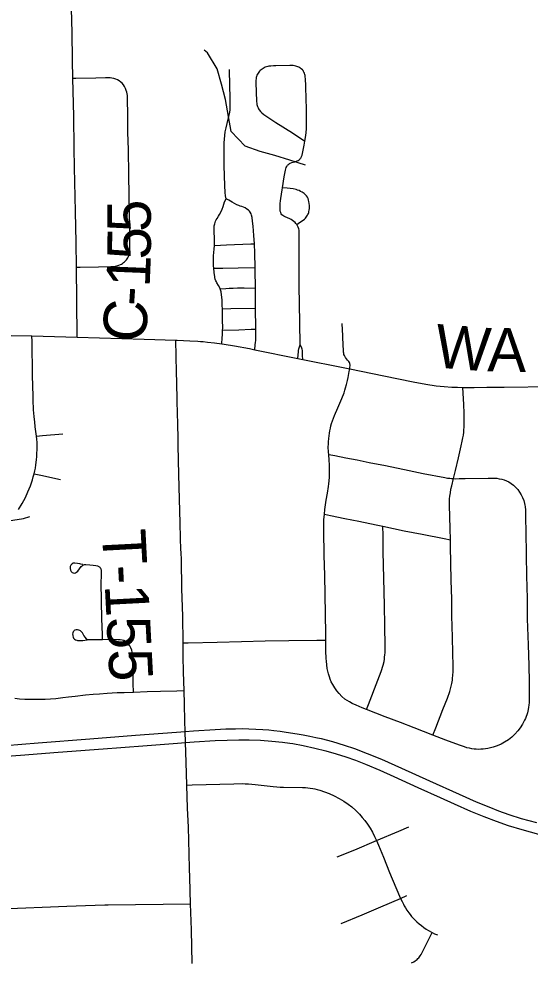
# Model space of a CAD drawing. Extents: x -6.4 to 34, y -4.2 to 22.
# Drawn here: x 5.927 to 6.594, y 17.467 to 18.698 of the extents above; entities that cross this region are included whole.
import ezdxf

# ---------------------------------------------------------------- set-up
doc = ezdxf.new("R2010")
doc.units = 0
for name, color, linetype in [('GM_X_County_Road', 7, 'Continuous'), ('GM_X_County_Road_Text', 7, 'Continuous'), ('GM_X_Minor_River', 7, 'Continuous'), ('GM_X_State_Route', 7, 'Continuous'), ('GM_X_Township_Road', 7, 'Continuous'), ('GM_X_Township_Road_Text', 7, 'Continuous')]:
    doc.layers.add(name, color=color, linetype=linetype)

msp = doc.modelspace()

# ---------------------------------------------------------------- linework, layer by layer
at = {"layer": 'GM_X_County_Road'}
for points in [[(6.0032, 18.2828), (6.0028, 18.3305), (6.0021, 18.3742), (6.0016, 18.4067), (6.0007, 18.4471), (5.9997, 18.5042), (5.9991, 18.5297), (5.9985, 18.5714), (5.9974, 18.6204), (5.9969, 18.6446), (5.9963, 18.6806), (5.9958, 18.7116)], [(5.9168, 18.2851), (5.9439, 18.2845), (6.0032, 18.2828), (6.0905, 18.2802), (6.1317, 18.279), (6.1334, 18.2789), (6.1502, 18.2783), (6.1607, 18.2777), (6.1639, 18.2774), (6.1676, 18.2771), (6.1731, 18.2766), (6.1824, 18.2757), (6.1918, 18.2744), (6.1948, 18.274), (6.2083, 18.2717), (6.2279, 18.268), (6.235, 18.2666), (6.2912, 18.2552), (6.2976, 18.2539), (6.3504, 18.2433), (6.3589, 18.2415), (6.4033, 18.2324), (6.4417, 18.2245), (6.4582, 18.2215), (6.4717, 18.2196), (6.4822, 18.2185), (6.4921, 18.2178), (6.4998, 18.2176), (6.5065, 18.2174), (6.5138, 18.2174), (6.5212, 18.2175), (6.538, 18.2177), (6.5604, 18.2179), (6.6226, 18.2185)]]:
    msp.add_lwpolyline(points, dxfattribs=at)
at = {"layer": 'GM_X_Minor_River'}
for points in [[(6.3012, 18.5073), (6.2808, 18.5139), (6.2611, 18.5201), (6.2418, 18.5251), (6.2226, 18.5324), (6.2041, 18.5515), (6.2005, 18.5709), (6.1965, 18.5929), (6.1913, 18.6131), (6.1857, 18.6332), (6.173, 18.6542), (6.1689, 18.6576)], [(5.9135, 18.0431), (5.9329, 18.0464), (5.9412, 18.0491)]]:
    msp.add_lwpolyline(points, dxfattribs=at)
at = {"layer": 'GM_X_State_Route'}
for points in [[(5.9096, 17.7503), (5.952, 17.7536), (6.0195, 17.7589), (6.0793, 17.7635), (6.1329, 17.7674), (6.1439, 17.7683), (6.1548, 17.7692), (6.183, 17.771), (6.1971, 17.7718), (6.2097, 17.7721), (6.2185, 17.7722), (6.2271, 17.772), (6.2361, 17.7716), (6.2455, 17.771), (6.2531, 17.7704), (6.2597, 17.7697), (6.2679, 17.7687), (6.276, 17.7676), (6.2902, 17.7654), (6.298, 17.7641), (6.3067, 17.7625), (6.3146, 17.7608), (6.3215, 17.7592), (6.3363, 17.7553), (6.3515, 17.7507), (6.365, 17.7462), (6.3818, 17.7398), (6.4002, 17.7322), (6.4263, 17.7206), (6.4631, 17.7039), (6.5017, 17.6866), (6.5239, 17.6768), (6.5405, 17.6699), (6.5533, 17.665), (6.5668, 17.6602), (6.5829, 17.6551), (6.6026, 17.6495)], [(6.0425, 17.7464), (6.0544, 17.7473), (6.1003, 17.7507), (6.1341, 17.7531), (6.1443, 17.7539), (6.156, 17.7548), (6.1831, 17.7566), (6.1989, 17.7573), (6.2139, 17.7577), (6.2276, 17.7576), (6.2425, 17.7569), (6.2573, 17.7559), (6.2711, 17.7544), (6.2808, 17.7531)], [(6.2808, 17.7531), (6.2846, 17.7526), (6.2983, 17.7501), (6.3132, 17.7468), (6.3276, 17.7433), (6.3413, 17.7394), (6.3539, 17.7355), (6.3664, 17.731), (6.3796, 17.7256), (6.398, 17.7179), (6.4163, 17.7099), (6.4479, 17.6955), (6.477, 17.6823), (6.4951, 17.6742), (6.5167, 17.6646), (6.5338, 17.6574), (6.5501, 17.6513), (6.5659, 17.6459), (6.5838, 17.6405), (6.6161, 17.6316), (6.6413, 17.6247), (6.6677, 17.6176), (6.6782, 17.6149)], [(5.7817, 17.7285), (5.798, 17.7291), (5.8313, 17.7309), (5.8489, 17.732), (5.8666, 17.733), (5.8939, 17.735), (5.9348, 17.7381), (5.9725, 17.741), (6.0135, 17.7442), (6.0425, 17.7464)]]:
    msp.add_lwpolyline(points, dxfattribs=at)
at = {"layer": 'GM_X_Township_Road'}
for points in [[(6.2793, 18.5089), (6.2803, 18.5095), (6.2813, 18.5099), (6.2835, 18.5107), (6.2873, 18.5119), (6.2901, 18.5129), (6.2916, 18.5137), (6.293, 18.5145), (6.2937, 18.5151), (6.2943, 18.5157), (6.2948, 18.5164), (6.2953, 18.5171), (6.2959, 18.5186), (6.2966, 18.5204), (6.2973, 18.5225), (6.2993, 18.5333), (6.3003, 18.5389), (6.3015, 18.5461), (6.302, 18.5501), (6.3025, 18.555), (6.3026, 18.5594), (6.3023, 18.5818), (6.3021, 18.5931), (6.3016, 18.6105), (6.3011, 18.6204), (6.3009, 18.6223), (6.3006, 18.6242), (6.3002, 18.6259), (6.2997, 18.6273), (6.2992, 18.6286), (6.2986, 18.6296), (6.2979, 18.6308), (6.2971, 18.6317), (6.2957, 18.6331), (6.2947, 18.6339), (6.2937, 18.6346), (6.2926, 18.6352), (6.2913, 18.6358), (6.2899, 18.6363), (6.2884, 18.6368), (6.2868, 18.6371), (6.285, 18.6373), (6.2832, 18.6375), (6.2807, 18.6375), (6.2626, 18.6372), (6.2592, 18.637), (6.2559, 18.6368), (6.2535, 18.6364), (6.2518, 18.6361), (6.2502, 18.6356), (6.2487, 18.6351), (6.2472, 18.6344), (6.2459, 18.6337), (6.2445, 18.6328), (6.2432, 18.6318), (6.242, 18.6308), (6.2411, 18.63), (6.2401, 18.6288), (6.2392, 18.6276), (6.2384, 18.6263), (6.2377, 18.6249), (6.2372, 18.6233), (6.2368, 18.6218), (6.2366, 18.6202), (6.2364, 18.6184), (6.2363, 18.6164), (6.2367, 18.6014), (6.2371, 18.5921), (6.2373, 18.5901), (6.2375, 18.5883), (6.2378, 18.5867), (6.2382, 18.5852), (6.2386, 18.5838), (6.2392, 18.5822), (6.2399, 18.5808), (6.2408, 18.5794), (6.2423, 18.5774), (6.2441, 18.5756), (6.2466, 18.5736), (6.2626, 18.5631), (6.284, 18.5496), (6.3003, 18.5389)], [(6.1821, 18.4284), (6.1827, 18.4308), (6.1831, 18.4326), (6.1837, 18.4343), (6.1845, 18.4362), (6.1857, 18.4378), (6.1877, 18.4408), (6.189, 18.4429), (6.1907, 18.4462), (6.1924, 18.45), (6.1936, 18.4535), (6.1946, 18.4565), (6.1956, 18.4594), (6.1976, 18.4634), (6.1968, 18.4676), (6.1963, 18.4717), (6.1957, 18.481), (6.1951, 18.5064), (6.195, 18.5151), (6.195, 18.5194), (6.1949, 18.5286), (6.1949, 18.5317), (6.195, 18.5366), (6.1953, 18.5415), (6.1964, 18.5507), (6.1975, 18.5561), (6.2004, 18.5676), (6.2019, 18.5743), (6.2027, 18.5793), (6.2029, 18.5827), (6.203, 18.585), (6.203, 18.5908), (6.2029, 18.5956), (6.2024, 18.6111), (6.2019, 18.6322)], [(6.0021, 18.3742), (6.007, 18.3742), (6.0308, 18.3746), (6.0469, 18.375), (6.0506, 18.3753), (6.0544, 18.3759), (6.056, 18.3763), (6.0576, 18.3769), (6.0595, 18.3777), (6.0611, 18.3784), (6.0624, 18.3792), (6.0637, 18.3802), (6.065, 18.3813), (6.0663, 18.3825), (6.0675, 18.3838), (6.0684, 18.3851), (6.0694, 18.3865), (6.0701, 18.3881), (6.0707, 18.3895), (6.0712, 18.391), (6.0715, 18.3925), (6.0717, 18.3941), (6.0719, 18.3976), (6.0719, 18.4014), (6.0719, 18.4112), (6.0716, 18.4259), (6.0713, 18.4451), (6.071, 18.4683), (6.0704, 18.495), (6.0699, 18.5279), (6.0694, 18.5502), (6.0693, 18.5708), (6.0688, 18.5957), (6.0686, 18.5981), (6.0683, 18.6005), (6.0678, 18.6027), (6.0671, 18.6049), (6.0662, 18.6073), (6.0649, 18.61), (6.0635, 18.6121), (6.0617, 18.6142), (6.0599, 18.6158), (6.0578, 18.6174), (6.0557, 18.6186), (6.0534, 18.6197), (6.0509, 18.6205), (6.0485, 18.621), (6.0462, 18.6212), (6.0401, 18.6212), (6.0275, 18.621), (6.0015, 18.6205), (5.9974, 18.6204)], [(6.2931, 18.4149), (6.2931, 18.4188), (6.293, 18.421), (6.2927, 18.4226), (6.2924, 18.4242), (6.2916, 18.4263), (6.2907, 18.4281), (6.2898, 18.4298), (6.2887, 18.4315), (6.2876, 18.4327), (6.2859, 18.4341), (6.284, 18.4354), (6.2823, 18.4364), (6.2806, 18.4373), (6.2744, 18.44), (6.2727, 18.4409), (6.2715, 18.4418), (6.2703, 18.4428), (6.2695, 18.4439), (6.2688, 18.4455), (6.2683, 18.4472), (6.2679, 18.4501), (6.2679, 18.4535), (6.2681, 18.4574), (6.2684, 18.4608), (6.2688, 18.4641), (6.2705, 18.4751), (6.271, 18.4779), (6.2735, 18.4921), (6.2743, 18.4965), (6.2752, 18.5007), (6.2757, 18.5026), (6.2761, 18.5042), (6.2766, 18.5056), (6.2772, 18.5066), (6.2776, 18.5073), (6.2783, 18.508), (6.2793, 18.5089)], [(6.2898, 18.4298), (6.2935, 18.4325), (6.2968, 18.4348), (6.2997, 18.4371), (6.3011, 18.4384), (6.3021, 18.4395), (6.303, 18.4407), (6.3039, 18.442), (6.3044, 18.4432), (6.305, 18.4444), (6.3053, 18.4457), (6.3056, 18.4469), (6.306, 18.4489), (6.3062, 18.4507), (6.3063, 18.4528), (6.3063, 18.4546), (6.306, 18.4574), (6.3057, 18.46), (6.3052, 18.4619), (6.3046, 18.4638), (6.3037, 18.4657), (6.3025, 18.4675), (6.3012, 18.4689), (6.2993, 18.4706), (6.2966, 18.4723), (6.2948, 18.4732), (6.2928, 18.4742), (6.2909, 18.475), (6.2888, 18.4756), (6.285, 18.4765), (6.2813, 18.4771), (6.2773, 18.4775), (6.271, 18.4779)], [(6.235, 18.2666), (6.2356, 18.2731), (6.2359, 18.2762), (6.2361, 18.2786), (6.2362, 18.2824), (6.2361, 18.2936), (6.2361, 18.2978), (6.236, 18.3175), (6.236, 18.321), (6.2359, 18.3305), (6.2357, 18.3469), (6.2354, 18.371), (6.2353, 18.3738), (6.2348, 18.3927), (6.2344, 18.4046), (6.2336, 18.4156), (6.2327, 18.428), (6.2321, 18.4342), (6.2315, 18.439), (6.2308, 18.442), (6.2302, 18.4438), (6.2289, 18.4459), (6.2279, 18.4473), (6.2267, 18.4487), (6.2247, 18.4502), (6.2224, 18.4516), (6.2204, 18.4526), (6.218, 18.4535), (6.2158, 18.4541), (6.2141, 18.4546), (6.2113, 18.4558), (6.2053, 18.4592), (6.201, 18.4616), (6.1976, 18.4634)], [(6.1918, 18.2744), (6.1924, 18.2822), (6.1927, 18.2859), (6.193, 18.2919), (6.1931, 18.2946), (6.193, 18.3057), (6.1926, 18.3201), (6.1924, 18.3244), (6.1923, 18.3319), (6.1917, 18.338), (6.1909, 18.3423), (6.1902, 18.3446), (6.1896, 18.3462), (6.1892, 18.3475), (6.1877, 18.3503), (6.1854, 18.354), (6.1848, 18.3551), (6.184, 18.3566), (6.1834, 18.3585), (6.1828, 18.3608), (6.1826, 18.362), (6.1823, 18.3644), (6.182, 18.3675), (6.1815, 18.3728), (6.1812, 18.376), (6.181, 18.3815), (6.1812, 18.389), (6.1818, 18.3977), (6.1822, 18.4028), (6.1823, 18.4052), (6.1822, 18.4126), (6.1821, 18.42), (6.182, 18.4259), (6.1821, 18.4284)], [(6.2943, 18.2728), (6.2939, 18.302), (6.293, 18.35), (6.2929, 18.3745), (6.2929, 18.4004), (6.2931, 18.4149)], [(6.1822, 18.4028), (6.1979, 18.4035), (6.2297, 18.4046), (6.2344, 18.4046)], [(6.1815, 18.3728), (6.1931, 18.3731), (6.2133, 18.3736), (6.2353, 18.3738)], [(6.1896, 18.3462), (6.1971, 18.3466), (6.2014, 18.3468), (6.2068, 18.347), (6.2123, 18.3472), (6.221, 18.3472), (6.2357, 18.3469)], [(6.1926, 18.3201), (6.2036, 18.3203), (6.236, 18.321)], [(6.193, 18.2919), (6.2141, 18.2927), (6.2301, 18.2933), (6.2361, 18.2936)], [(6.3589, 18.2415), (6.3592, 18.2438), (6.3593, 18.2454), (6.3593, 18.2467), (6.3592, 18.2479), (6.3589, 18.249), (6.3584, 18.25), (6.3577, 18.2511), (6.3562, 18.253), (6.3536, 18.2564), (6.352, 18.2591), (6.3514, 18.2605), (6.351, 18.262), (6.3508, 18.2635), (6.3506, 18.2651), (6.3506, 18.2674), (6.3503, 18.2713), (6.3497, 18.2849), (6.3492, 18.301)], [(5.9266, 18.0581), (5.9312, 18.066), (5.9354, 18.0738), (5.9388, 18.081), (5.942, 18.0891), (5.9446, 18.0966), (5.9458, 18.1008), (5.9468, 18.1047), (5.9477, 18.1085), (5.9485, 18.1122), (5.9491, 18.1162), (5.9496, 18.1195), (5.95, 18.1232), (5.9503, 18.1269), (5.9505, 18.1312), (5.9507, 18.1362), (5.9507, 18.141), (5.9506, 18.1454), (5.9504, 18.1497), (5.95, 18.1538), (5.9484, 18.166), (5.9477, 18.1723), (5.947, 18.1788), (5.9465, 18.1844), (5.9462, 18.1878), (5.9461, 18.1911), (5.9458, 18.198), (5.9455, 18.2061), (5.9448, 18.2328), (5.9441, 18.2775), (5.9439, 18.2845)], [(6.1534, 17.4657), (6.1521, 17.5098), (6.1511, 17.5436), (6.15, 17.5781), (6.1497, 17.5898), (6.1492, 17.609), (6.1482, 17.6436), (6.1473, 17.6684), (6.1464, 17.6986), (6.1453, 17.7284), (6.1443, 17.7539), (6.1439, 17.7683), (6.1436, 17.7824), (6.143, 17.8042), (6.1426, 17.8219), (6.142, 17.8457), (6.1416, 17.8668), (6.1414, 17.8841), (6.141, 17.9187), (6.1402, 17.9428), (6.1399, 17.9546), (6.1392, 17.9924), (6.1387, 18.0022), (6.1385, 18.0059), (6.138, 18.0206), (6.1374, 18.0405), (6.1366, 18.0716), (6.1358, 18.1039), (6.1351, 18.1415), (6.135, 18.149), (6.1344, 18.1713), (6.134, 18.1825), (6.1335, 18.2008), (6.1331, 18.2237), (6.1327, 18.2373), (6.1317, 18.279)], [(6.2912, 18.2552), (6.2916, 18.2598), (6.2919, 18.2638), (6.292, 18.2657), (6.2924, 18.2676), (6.2928, 18.269), (6.2932, 18.2702), (6.2943, 18.2728)], [(6.2976, 18.2539), (6.2974, 18.2589), (6.2972, 18.2635), (6.2971, 18.2654), (6.2968, 18.2672), (6.2964, 18.2686), (6.2958, 18.27), (6.2943, 18.2728)], [(6.4944, 18.0984), (6.4976, 18.0983), (6.5016, 18.0984), (6.5096, 18.0987), (6.5397, 18.0991), (6.5471, 18.0989), (6.5508, 18.0988), (6.554, 18.0983), (6.5573, 18.0978), (6.5604, 18.0969), (6.5634, 18.0956), (6.5667, 18.094), (6.5699, 18.0921), (6.5727, 18.0899), (6.5754, 18.0873), (6.5783, 18.0841), (6.5807, 18.0808), (6.5829, 18.0773), (6.5847, 18.0738), (6.5862, 18.0699), (6.5872, 18.066), (6.5877, 18.0639), (6.588, 18.0618), (6.5882, 18.0573), (6.5884, 18.0465), (6.5888, 18.0297), (6.5894, 17.9984), (6.5899, 17.9715), (6.5904, 17.9421), (6.5908, 17.9156), (6.5918, 17.8814), (6.5926, 17.8547), (6.593, 17.8332), (6.5932, 17.8234), (6.5933, 17.8156), (6.5933, 17.8093), (6.5931, 17.8062), (6.5928, 17.8029), (6.5924, 17.8002), (6.5919, 17.7971), (6.5914, 17.795), (6.5909, 17.7928), (6.59, 17.7901), (6.5893, 17.7878), (6.5883, 17.7855), (6.5872, 17.7831), (6.5844, 17.778), (6.5814, 17.7733), (6.5782, 17.7691), (6.5745, 17.7648), (6.5704, 17.761), (6.566, 17.7575), (6.5612, 17.7545), (6.5565, 17.7519), (6.5515, 17.7498), (6.5462, 17.748), (6.5426, 17.7471), (6.5393, 17.7463), (6.5362, 17.7458), (6.5331, 17.7454), (6.5302, 17.7452), (6.5273, 17.7451), (6.5242, 17.7452), (6.5212, 17.7454), (6.5182, 17.7458), (6.5153, 17.7465), (6.512, 17.7473), (6.5087, 17.7483), (6.5023, 17.7505), (6.4846, 17.7571), (6.4674, 17.7637), (6.4429, 17.7732), (6.4253, 17.78), (6.4052, 17.7877), (6.3808, 17.7971), (6.3752, 17.7993), (6.3673, 17.8026), (6.3623, 17.805), (6.3584, 17.8072), (6.3556, 17.8089), (6.3527, 17.8108), (6.3488, 17.8141), (6.3452, 17.8178), (6.342, 17.8215), (6.3393, 17.8253), (6.3367, 17.8296), (6.3347, 17.8333), (6.3334, 17.8367), (6.3323, 17.8396), (6.331, 17.8436), (6.3302, 17.8471), (6.3295, 17.8508), (6.3288, 17.8556), (6.3285, 17.86), (6.3283, 17.8637), (6.3279, 17.8736), (6.3277, 17.8878), (6.3276, 17.8956), (6.3272, 17.9221), (6.3262, 17.9718), (6.3255, 17.9985), (6.325, 18.0302), (6.3249, 18.0364), (6.3253, 18.0444), (6.3259, 18.0518), (6.3265, 18.058), (6.3273, 18.064), (6.3282, 18.0703), (6.3299, 18.0794), (6.3314, 18.088), (6.3318, 18.0918), (6.3324, 18.0999), (6.3325, 18.1047), (6.3325, 18.1099), (6.3324, 18.1162), (6.3321, 18.1223), (6.3315, 18.13), (6.3312, 18.1328), (6.3309, 18.1399), (6.331, 18.1435), (6.3311, 18.1466), (6.3315, 18.1507), (6.3319, 18.1543), (6.3324, 18.1579), (6.333, 18.1609), (6.3336, 18.1641), (6.3344, 18.1671), (6.3353, 18.1704), (6.3363, 18.1736), (6.3389, 18.1806), (6.3434, 18.1908), (6.3487, 18.2028), (6.3515, 18.2103), (6.3527, 18.2137), (6.3536, 18.2169), (6.3548, 18.2214), (6.3559, 18.2263), (6.3568, 18.2305), (6.3583, 18.2382), (6.3589, 18.2415)], [(6.4674, 17.7637), (6.4713, 17.7733), (6.4805, 17.7971), (6.4864, 17.812), (6.4895, 17.8206), (6.4911, 17.8259), (6.4922, 17.8309), (6.4929, 17.8355), (6.4932, 17.8383), (6.4935, 17.8411), (6.4938, 17.8471), (6.4938, 17.854), (6.4935, 17.8705), (6.493, 17.8914), (6.4924, 17.9194), (6.4921, 17.9413), (6.4915, 17.9657), (6.491, 17.9879), (6.4906, 18.0103), (6.4904, 18.0185), (6.4901, 18.0334), (6.4892, 18.0639), (6.4892, 18.0683), (6.4893, 18.0718), (6.4896, 18.0756), (6.4903, 18.0799), (6.4911, 18.0845), (6.4921, 18.0889), (6.4944, 18.0984), (6.497, 18.1088), (6.5008, 18.1254), (6.5044, 18.141), (6.5058, 18.1472), (6.5066, 18.1514), (6.5073, 18.1553), (6.5078, 18.1589), (6.5081, 18.1621), (6.5083, 18.1656), (6.5084, 18.1698), (6.5085, 18.1741), (6.5085, 18.1789), (6.5083, 18.184), (6.5077, 18.1953), (6.5069, 18.2101), (6.5065, 18.2174)], [(5.95, 18.1538), (5.9576, 18.1545), (5.9843, 18.1569)], [(6.3315, 18.13), (6.3393, 18.1285), (6.354, 18.1256), (6.3686, 18.1227), (6.3843, 18.1195), (6.4055, 18.1153), (6.4366, 18.109), (6.455, 18.1052), (6.483, 18.0998), (6.4865, 18.0992), (6.4894, 18.0988), (6.4917, 18.0986), (6.4944, 18.0984)], [(5.9468, 18.1047), (5.9555, 18.1027), (5.9814, 18.0971)], [(6.3259, 18.0518), (6.3339, 18.0504), (6.3526, 18.0465), (6.3706, 18.0428), (6.3934, 18.0381), (6.4023, 18.0362), (6.43, 18.0304), (6.4535, 18.0257), (6.482, 18.0201), (6.4904, 18.0185)], [(6.3808, 17.7971), (6.3833, 17.8036), (6.3958, 17.8354), (6.3998, 17.8465), (6.4025, 17.8549), (6.4037, 17.8597), (6.4042, 17.8626), (6.4045, 17.8653), (6.4049, 17.8685), (6.4051, 17.8712), (6.4052, 17.8737), (6.4052, 17.8791), (6.4048, 17.9071), (6.4043, 17.9325), (6.4038, 17.9512), (6.4026, 18.0027), (6.4024, 18.024), (6.4023, 18.0362)], [(6.0104, 17.9862), (6.008, 17.9868), (6.0065, 17.9872), (6.0034, 17.9878), (6.0002, 17.9882), (5.998, 17.9879), (5.9967, 17.9873), (5.9955, 17.9864), (5.9946, 17.9853), (5.994, 17.9839), (5.9937, 17.9825), (5.9938, 17.9811), (5.9943, 17.979), (5.9954, 17.9772), (5.9965, 17.9761), (5.9979, 17.9754), (5.9994, 17.9752), (6.0009, 17.9755), (6.0022, 17.9762), (6.0038, 17.9776), (6.0061, 17.9807), (6.0082, 17.9836), (6.0094, 17.9848), (6.0108, 17.9857), (6.0116, 17.986), (6.0124, 17.9862), (6.0134, 17.9863), (6.0143, 17.9863), (6.0195, 17.986), (6.0241, 17.9855), (6.0275, 17.985), (6.0298, 17.9845), (6.0305, 17.9842), (6.0313, 17.9838), (6.0319, 17.9834), (6.0325, 17.9828), (6.0331, 17.9822)], [(6.0363, 17.8882), (6.0361, 17.8949), (6.0353, 17.9154), (6.0348, 17.9385), (6.0343, 17.9634), (6.0347, 17.9709), (6.0349, 17.9752), (6.0349, 17.9775), (6.0348, 17.9788), (6.0345, 17.9797), (6.034, 17.981), (6.0336, 17.9816), (6.0331, 17.9822)], [(6.0765, 17.8198), (6.0762, 17.8311), (6.0755, 17.8543), (6.0752, 17.865), (6.0748, 17.8718), (6.0743, 17.8747), (6.0733, 17.8775), (6.072, 17.8801), (6.0702, 17.8825), (6.0681, 17.8846), (6.0662, 17.8859), (6.0641, 17.887), (6.0619, 17.8877), (6.059, 17.8881), (6.0563, 17.8882), (6.0469, 17.8883), (6.0363, 17.8882), (6.0161, 17.888), (6.0137, 17.891), (6.0119, 17.8937), (6.0104, 17.8962), (6.0098, 17.8973), (6.0092, 17.8982), (6.008, 17.8994), (6.0073, 17.8999), (6.0067, 17.9003), (6.0051, 17.9008), (6.0035, 17.9011), (6.0018, 17.901), (6.0002, 17.9006), (5.9993, 17.9001), (5.9985, 17.8994), (5.9979, 17.8986), (5.9973, 17.8971), (5.9971, 17.8955), (5.9972, 17.8945), (5.9973, 17.8932), (5.9977, 17.8915), (5.9984, 17.8901), (5.9994, 17.8889), (6.0008, 17.8881), (6.0024, 17.8875), (6.0035, 17.8872), (6.0064, 17.887), (6.0084, 17.887), (6.0104, 17.8872), (6.0161, 17.888)], [(6.1414, 17.8841), (6.1478, 17.8842), (6.186, 17.885), (6.2177, 17.8858), (6.2487, 17.8866), (6.2795, 17.8873), (6.3158, 17.8878), (6.3277, 17.8878)], [(5.9217, 17.8117), (5.9276, 17.8112), (5.9349, 17.8108), (5.9469, 17.8105), (5.9537, 17.8104), (5.9611, 17.8106), (5.9684, 17.811), (5.9753, 17.8116), (5.9845, 17.8127), (5.9918, 17.8135), (6.0004, 17.8146), (6.014, 17.8161), (6.0239, 17.817), (6.0321, 17.8176), (6.0422, 17.8184), (6.0552, 17.8191), (6.0644, 17.8195), (6.0765, 17.8198), (6.0946, 17.8204), (6.112, 17.8209), (6.1332, 17.8216), (6.1426, 17.8219)], [(6.1464, 17.6986), (6.1531, 17.6988), (6.2076, 17.7003), (6.2183, 17.7004), (6.2226, 17.7003), (6.2268, 17.7), (6.2355, 17.6993), (6.2473, 17.698), (6.259, 17.6966), (6.2637, 17.6962), (6.2682, 17.6959), (6.2726, 17.6957), (6.2974, 17.6953), (6.3013, 17.6953), (6.3044, 17.6949), (6.3074, 17.6945), (6.3107, 17.6939), (6.3134, 17.6934), (6.3162, 17.6928), (6.3197, 17.6918), (6.3258, 17.6898), (6.3322, 17.6873), (6.3388, 17.6844), (6.3452, 17.6811), (6.3513, 17.6775), (6.3569, 17.6738), (6.3618, 17.6699), (6.3668, 17.6652), (6.3715, 17.6605), (6.3752, 17.6563), (6.3786, 17.6522), (6.3822, 17.6474), (6.3855, 17.6424), (6.3886, 17.6371), (6.3914, 17.6315), (6.3937, 17.626), (6.3963, 17.6202), (6.4028, 17.6046), (6.411, 17.5846), (6.4192, 17.565), (6.4254, 17.5506), (6.4272, 17.5467), (6.4289, 17.5433), (6.4302, 17.5408), (6.4316, 17.5384), (6.4335, 17.5354), (6.436, 17.5319), (6.4379, 17.5295), (6.4397, 17.5272), (6.4418, 17.5249), (6.4441, 17.5226), (6.4467, 17.5201), (6.4497, 17.5176), (6.4526, 17.5151), (6.4558, 17.5127), (6.4589, 17.5106), (6.4619, 17.5087), (6.4665, 17.5063), (6.4698, 17.5046), (6.4734, 17.503)], [(6.3937, 17.626), (6.423, 17.6383), (6.4362, 17.644)], [(6.3426, 17.6049), (6.3657, 17.6142), (6.3937, 17.626)], [(6.3476, 17.5177), (6.3753, 17.5292), (6.3996, 17.5395), (6.4254, 17.5506), (6.4333, 17.5542)], [(5.9038, 17.5372), (5.9894, 17.5403), (6.0141, 17.5412), (6.0393, 17.5421), (6.0435, 17.5421), (6.1511, 17.5436)], [(6.4397, 17.4665), (6.4424, 17.4679), (6.4442, 17.469), (6.4455, 17.4699), (6.4469, 17.4709), (6.448, 17.472), (6.449, 17.4732), (6.4501, 17.4745), (6.451, 17.4758), (6.4521, 17.4776), (6.453, 17.4792), (6.4573, 17.4879), (6.4626, 17.4985), (6.4665, 17.5063)]]:
    msp.add_lwpolyline(points, dxfattribs=at)

# ---------------------------------------------------------------- texts
at = {"layer": 'GM_X_County_Road_Text'}
for s, rotation, p in [('5', 90.5006, (6.0994, 18.4204)), ('5', 89.3548, (6.0991, 18.3841)), ('1', 87.6196, (6.0976, 18.3473)), ('-', 86.1933, (6.0959, 18.3224)), ('C', 85.4208, (6.0921, 18.2751)), ('W', 355.5509, (6.4689, 18.2436)), ('A', 359.0222, (6.5383, 18.2384))]:
    msp.add_text(s, height=0.0568, rotation=rotation, dxfattribs=at).set_placement(p)
at = {"layer": 'GM_X_Township_Road_Text'}
msp.add_text('T-155', height=0.05682, rotation=273.0037, dxfattribs=at).set_placement((6.0353, 18.031))

doc.saveas('drawing.dxf')
